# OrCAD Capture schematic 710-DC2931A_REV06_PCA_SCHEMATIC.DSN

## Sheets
1 PAGE2
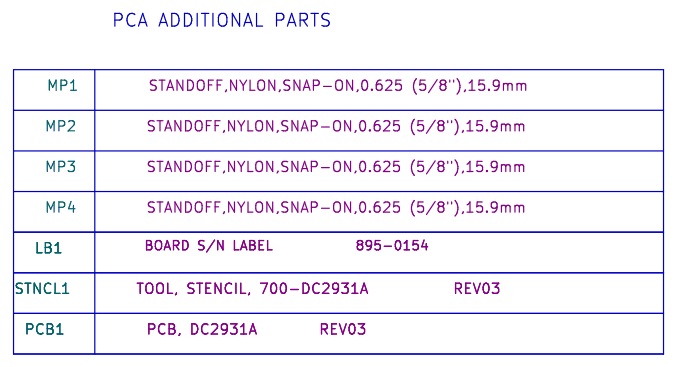
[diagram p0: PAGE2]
2 PAGE1: size Custom; note: HIGH EFFICIENCY BUCK-BOOST CONVERTER
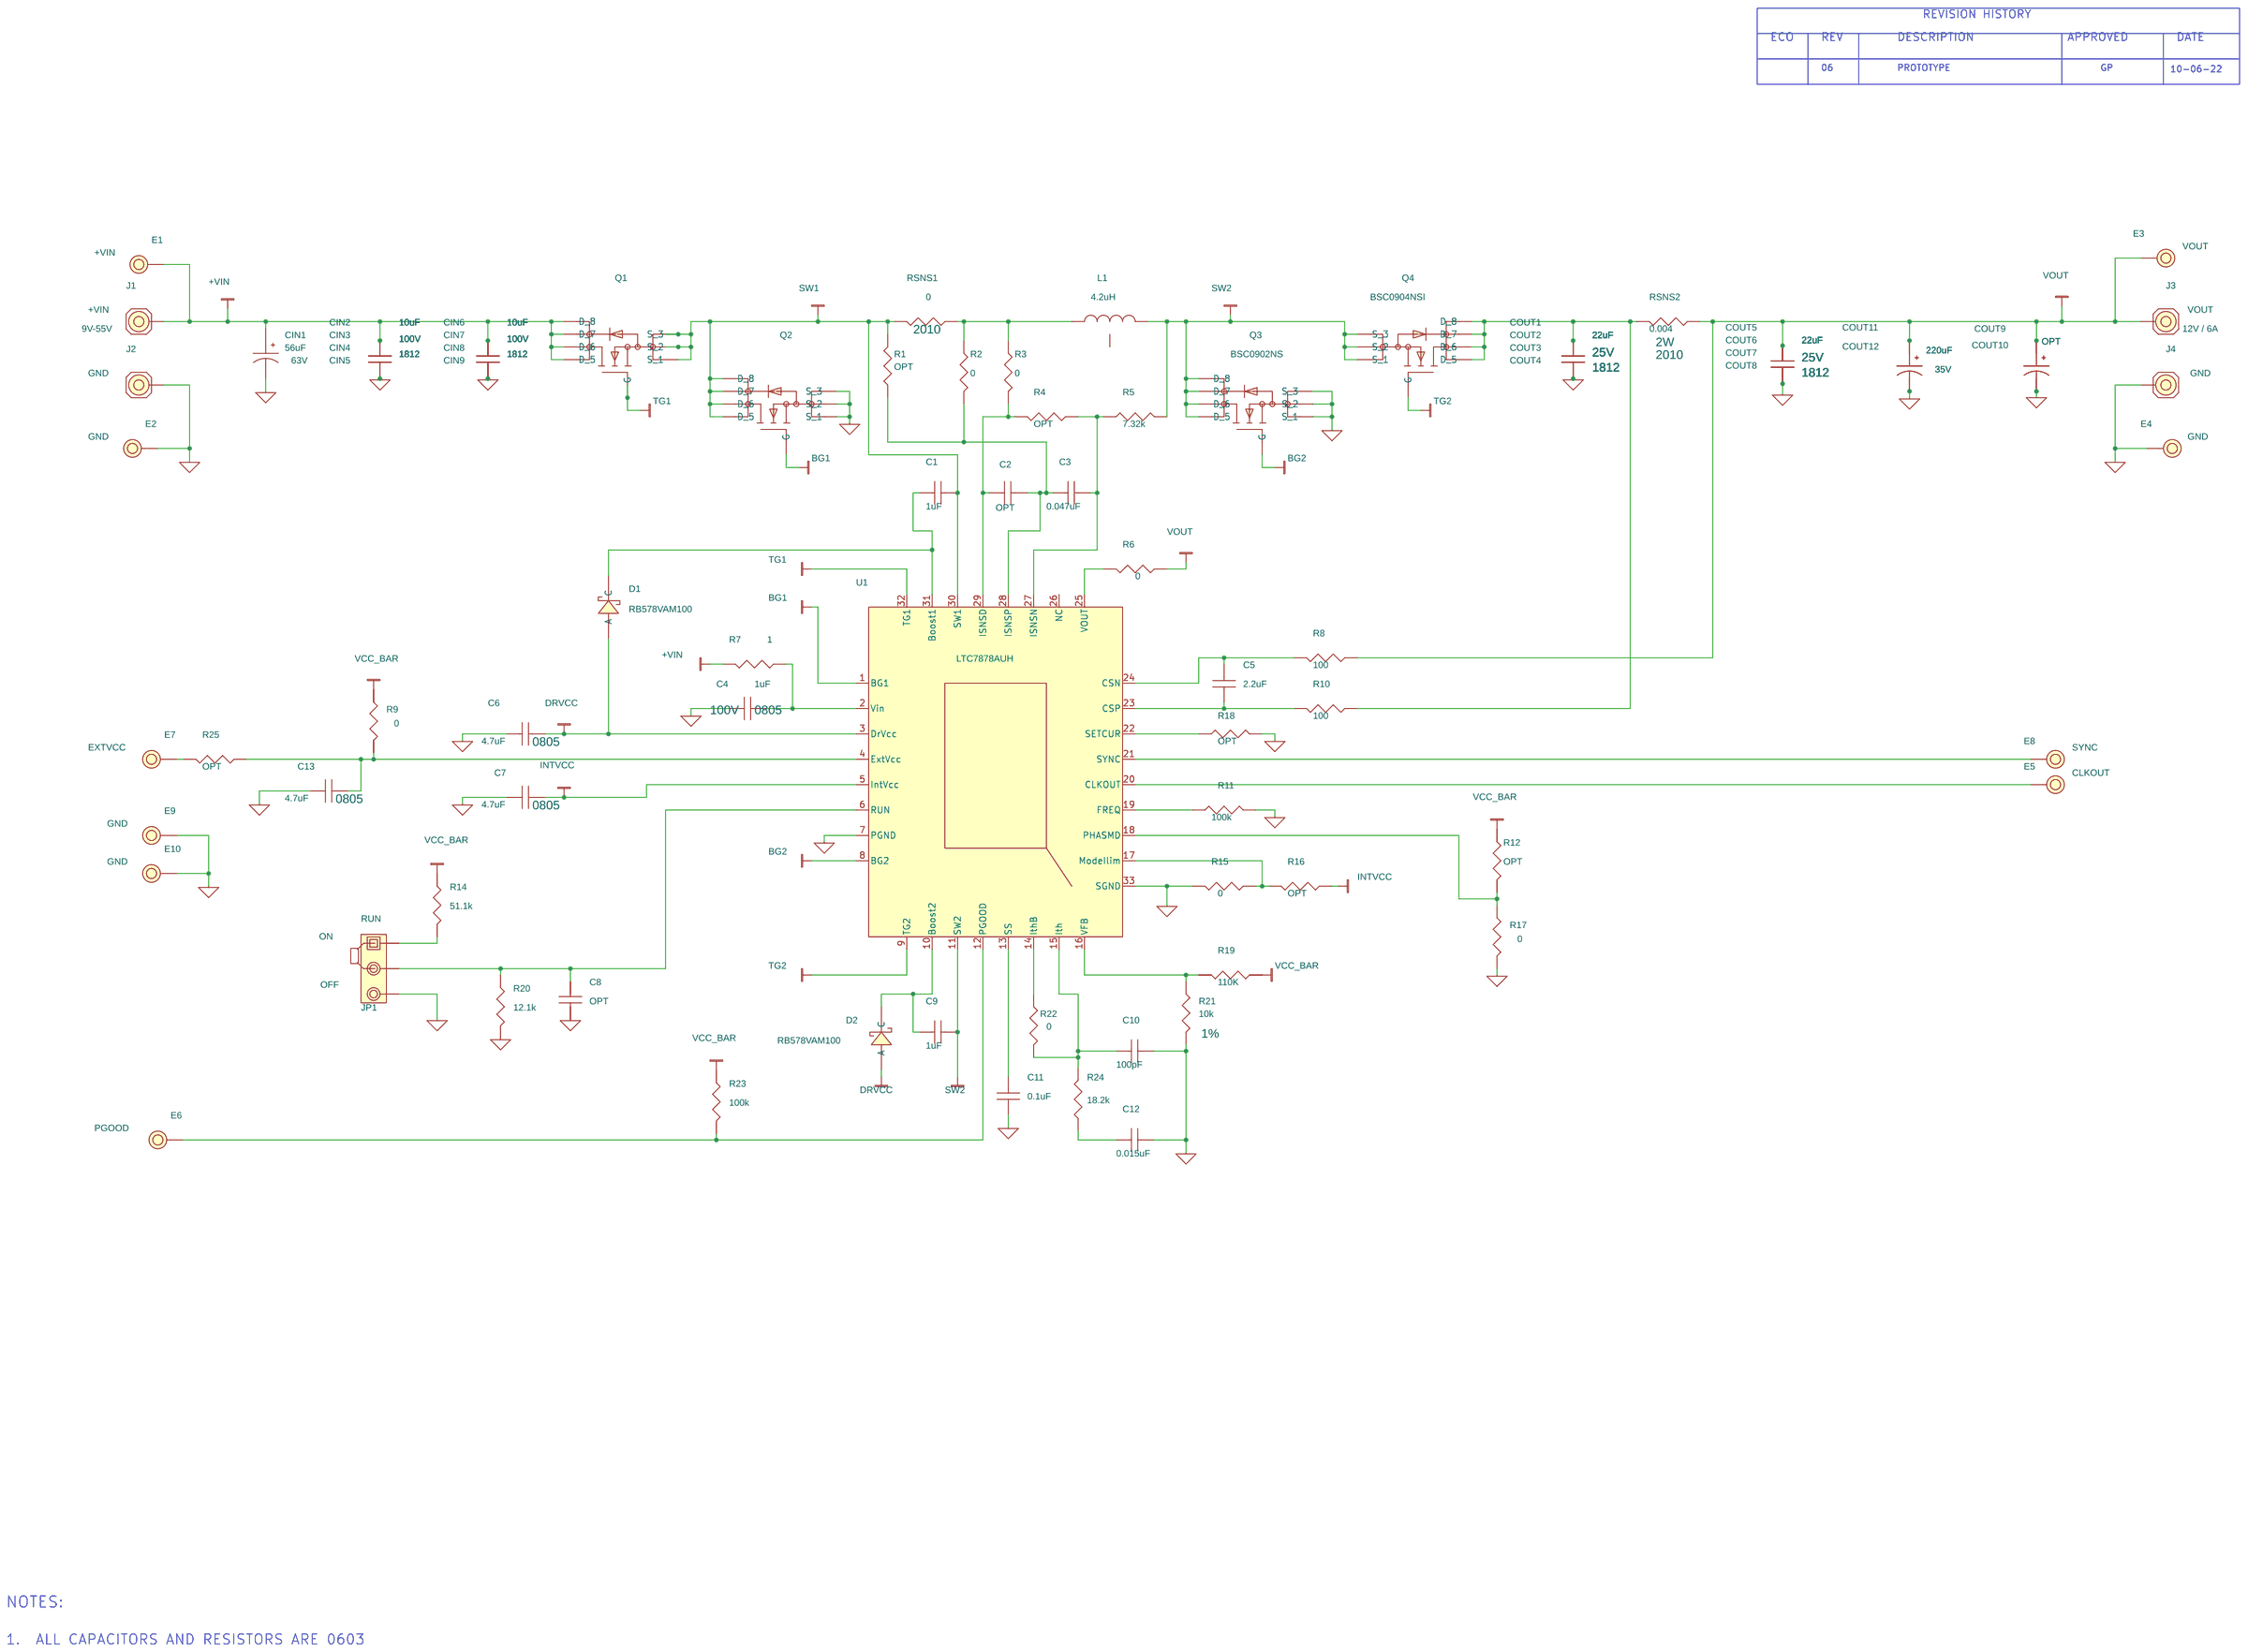
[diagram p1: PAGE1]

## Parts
sheet PAGE1
C1  1uF  [CC0603N]
C2  OPT  [CC0603N]
C3  0.047uF  [CC0603N]
C4  1uF  [CC0805N]
C5  2.2uF  [CC0603N]
C6  4.7uF  [CC0805N]
C7  4.7uF  [CC0805N]
C8  OPT  [CC0603N]
C9  1uF  [CC0603N]
C10  100pF  [CC0603N]
C11  0.1uF  [CC0603N]
C12  0.015uF  [CC0603N]
C13  4.7uF  [CC0805N]
CIN1  56uF  [PANASONIC_ZC_10X10.2]
CIN2  10uF  [CC1812N]
CIN3  10uF  [CC1812N]
CIN4  10uF  [CC1812N]
CIN5  10uF  [CC1812N]
CIN6  10uF  [CC1812N]
CIN7  10uF  [CC1812N]
CIN8  10uF  [CC1812N]
CIN9  10uF  [CC1812N]
COUT1  22uF  [CC1812N]
COUT2  22uF  [CC1812N]
COUT3  22uF  [CC1812N]
COUT4  22uF  [CC1812N]
COUT5  22uF  [CC1812N]
COUT6  22uF  [CC1812N]
COUT7  22uF  [CC1812N]
COUT8  22uF  [CC1812N]
COUT9  OPT  [USER_ASSIGNED]
COUT10  OPT  [USER_ASSIGNED]
COUT11  220uF  [SUNCON_HVH_10X12.5]
COUT12  220uF  [SUNCON_HVH_10X12.5]
D1  RB578VAM100  [ROHM-SOD-323HE]
D2  RB578VAM100  [ROHM-SOD-323HE]
E1  TEST POINT  [MILLMAX2501]
E2  TEST POINT  [MILLMAX2501]
E3  TEST POINT  [MILLMAX2501]
E4  TEST POINT  [MILLMAX2501]
E5  TEST POINT  [MILLMAX2501]
E6  TEST POINT  [MILLMAX2501]
E7  TEST POINT  [MILLMAX2501]
E8  TEST POINT  [MILLMAX2501]
E9  TEST POINT  [MILLMAX2501]
E10  TEST POINT  [MILLMAX2501]
J1  STUD,#10-32  [PENN-KFH-032]
J2  STUD,#10-32  [PENN-KFH-032]
J3  STUD,#10-32  [PENN-KFH-032]
J4  STUD,#10-32  [PENN-KFH-032]
JP1  HDR  [HD1X3-079]
L1  4.2uH  [WURTH-2013]
Q1  8P_N-CH_TYPE1A  [INFINEON-PG-TDSON-8]
Q2  8P_N-CH_TYPE1A  [INFINEON-PG-TDSON-8]
Q3  BSC0902NS  [INFINEON-PG-TDSON-8]
Q4  BSC0904NSI  [INFINEON-PG-TDSON-8]
R1  OPT  [CR0603N]
R2  0  [CR0603N]
R3  0  [CR0603N]
R4  OPT  [CR0603N]
R5  7.32k  [CR0603N]
R6  0  [CR0603N]
R7  1  [CR0603N]
R8  100  [CR0603N]
R9  0  [CR0603N]
R10  100  [CR0603N]
R11  100k  [CR0603N]
R12  OPT  [CR0603N]
R14  51.1k  [CR0603N]
R15  0  [CR0603N]
R16  OPT  [CR0603N]
R17  0  [CR0603N]
R18  OPT  [CR0603N]
R19  110K  [CR0603N]
R20  12.1k  [CR0603N]
R21  10k  [CR0603N]
R22  0  [CR0603N]
R23  100k  [CR0603N]
R24  18.2k  [CR0603N]
R25  OPT  [CR0603N]
RSNS1  0  [CR2010N]
RSNS2  0.004  [VISHAY-WSL2010_T58]
U1  LTC7878AUH  [LTC-UH-32-1693]
XJP1  SHUNT
sheet PAGE2
LB1  LABEL  [895-0154_REV01]
MP1  STANDOFF  [KEYSTONE_8829-8834]
MP2  STANDOFF  [KEYSTONE_8829-8834]
MP3  STANDOFF  [KEYSTONE_8829-8834]
MP4  STANDOFF  [KEYSTONE_8829-8834]
MP5  RING,LUG,#10,CRIMP
PCB1  PCB, DC2931A  [MECHANICAL_PART]
STNCL1  TOOL, STENCIL, 700-DC2931A

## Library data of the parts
C1 C9 = CAP: CAP.,1uF,X7R,16V,10%,0603; CLASS: DISCRETE; Dielectric Type: X7R; FPLIST: CC0603N,CC0603L,CC0603M; Inventory Qty: 29099; Manufacturer: KEMET; Manufacturer PN: C0603C105K4RAC7867; PART_NUMBER: 150-0179; Package Size: 0603; Rated Voltage: 16V; Tolerance: 10%
C2 C8 = CAP: CAP., OPTION, 0603; CLASS: DISCRETE; FPLIST: CC0603N,CC0603L,CC0603M; PART_NUMBER: 150-3038; Package Size: 0603; Package Type: SMD
C3 = CAP: CAP.,0.047uF,X7R,16V,10%,0603; CLASS: DISCRETE; Dielectric Type: X7R; FPLIST: CC0603N,CC0603L,CC0603M; Inventory Qty: 24676; Manufacturer: AVX; Manufacturer PN: 0603YC473KAT2A; PART_NUMBER: 150-3198; Package Size: 0603; Rated Voltage: 16V; Tolerance: 10%
C4 = CAP: CAP.,1uF,X7S,100V,20%,0805; CLASS: DISCRETE; Dielectric Type: X7S; FPLIST: CC0805N,CC0805L,CC0805M; Inventory Qty: 8512; Manufacturer: MURATA; Manufacturer PN: GRJ21BC72A105ME11L; PART_NUMBER: 150-2447; Package Size: 0805; Rated Voltage: 100V; Tolerance: 20%
C5 = CAP: CAP.,2.2uF,X5R,16V,10%,0603; CLASS: DISCRETE; Dielectric Type: X5R; FPLIST: CC0603N,CC0603L,CC0603M; Inventory Qty: 19450; Manufacturer: KEMET; Manufacturer PN: C0603C225K4PAC7867; PART_NUMBER: 150-0552; Package Size: 0603; Rated Voltage: 16V; Tolerance: 10%
C6 C7 C13 = CAP: CAP.,4.7uF,X5R,50V,10%,0805; CLASS: DISCRETE; Dielectric Type: X5R; FPLIST: CC0805N,CC0805L,CC0805M; Inventory Qty: 14038; Manufacturer: MURATA; Manufacturer PN: GRM21BR61H475KE51L; PART_NUMBER: 150-0172; Package Size: 0805; Rated Voltage: 50V; Tolerance: 10%
C10 = CAP: CAP.,100pF,X7R,25V,5%,0603; CLASS: DISCRETE; Dielectric Type: X7R; FPLIST: CC0603N,CC0603L,CC0603M; Inventory Qty: 38271; Manufacturer: AVX; Manufacturer PN: 06033C101JAT2A; PART_NUMBER: 150-0122; Package Size: 0603; Rated Voltage: 25V; Tolerance: 5%
C11 = CAP: CAP.,0.1uF,X7R,16V,10%,0603; CLASS: DISCRETE; Dielectric Type: X7R; FPLIST: CC0603N,CC0603L,CC0603M; Inventory Qty: 34669; Manufacturer: MURATA; Manufacturer PN: GRM188R71C104KA01D; PART_NUMBER: 150-0018; Package Size: 0603; Package Type: SMD; Rated Voltage: 16V; Tolerance: 10%
C12 = CAP: CAP.,0.015uF,X7R,25V,10%,0603; CLASS: DISCRETE; Dielectric Type: X7R; FPLIST: CC0603N,CC0603L,CC0603M; Inventory Qty: 32248; Manufacturer: AVX; Manufacturer PN: 06033C153KAT2A; PART_NUMBER: 150-3277; Package Size: 0603; Rated Voltage: 25V; Tolerance: 10%
CIN1 = CAP_P: CAP.,56uF,ALUM.ELECT.,63V,20%,10X10.2mm SMD, RADIAL,AEC-Q200; CLASS: DISCRETE; Dielectric Type: ALUM.ELECT.; Inventory Qty: 2000; Manufacturer: PANASONIC; Manufacturer PN: EEHZC1J560P; PART_NUMBER: 150-0727; Package Size: 10X10.2mm SMD, RADIAL; Rated Voltage: 63V; Tolerance: 20%
CIN2-CIN9 = CAP: CAP.,10uF,X7S,100V,20%,1812; CLASS: DISCRETE; Dielectric Type: X7S; FPLIST: CC1812N,CC1812L,CC1812M; Inventory Qty: 3000; Manufacturer: TDK; Manufacturer PN: CKG45NX7S2A106M500JH; PART_NUMBER: 150-0534; Package Size: 1812; Rated Voltage: 100V; Tolerance: 20%
COUT1-COUT8 = CAP: CAP.,22uF,X5R,25V,20%,1812; CLASS: DISCRETE; Dielectric Type: X5R; FPLIST: CC1812N,CC1812L,CC1812M; Inventory Qty: 4600; Manufacturer: TDK; Manufacturer PN: C4532X5R1E226M250KA; PART_NUMBER: 150-3272; Package Size: 1812; Rated Voltage: 25V; Tolerance: 20%
COUT9 COUT10 = CAP_P: CAP.,OPTION,ALUM. ELECT.,SMD; CLASS: DISCRETE; PART_NUMBER: 150-3568; Package Type: SMD
COUT11 COUT12 = CAP_P: CAP.,220uF,ALUM POLY HYB,35V,20%,10x12.5mm,SMD,RADIAL,HVH Series,AEC-Q200; CLASS: DISCRETE; Dielectric Type: ALUM POLY HYB; FPLIST: SUNCON_HVH_10X12.5,SUNCON_HVH_10X12-5; Inventory Qty: 5100; Manufacturer: SUN ELECTRONIC INDUSTRIES CORP; Manufacturer PN: 35HVH220M; PART_NUMBER: 150-0485; Package Size: 10x12.5mm,SMD,RADIAL; Rated Voltage: 35V; Tolerance: 20%
D1 D2 = DIODE_SCHOTTKY_A: DIODE,SCHOTTKY,100V,0.7A,SOD-323HE; CLASS: DISCRETE; Inventory Qty: 0; Manufacturer: ROHM; Manufacturer PN: RB578VAM100TR; PART_NUMBER: 210-0585; Package Size: 2-SMD, Flat Lead; Package Type: SOD-323HE; Rated Voltage or Zener Voltage: 100V
E1 = TESTPOINT_.219_MILL-MAX_2501: TEST POINT,TURRET,0.094" MTG. HOLE,PCB 0.062" THK; CLASS: IO; Inventory Qty: 823526; Manufacturer: MILL-MAX; Manufacturer PN: 2501-2-00-80-00-00-07-0; PART_FIELD_01: +VIN; PART_NUMBER: 260-0003
E2 E4 E9 E10 = TESTPOINT_.219_MILL-MAX_2501: TEST POINT,TURRET,0.094" MTG. HOLE,PCB 0.062" THK; CLASS: IO; Inventory Qty: 823526; Manufacturer: MILL-MAX; Manufacturer PN: 2501-2-00-80-00-00-07-0; PART_FIELD_01: GND; PART_NUMBER: 260-0003
E3 = TESTPOINT_.219_MILL-MAX_2501: TEST POINT,TURRET,0.094" MTG. HOLE,PCB 0.062" THK; CLASS: IO; Inventory Qty: 823526; Manufacturer: MILL-MAX; Manufacturer PN: 2501-2-00-80-00-00-07-0; PART_FIELD_01: VOUT; PART_NUMBER: 260-0003
E5 = TESTPOINT_.219_MILL-MAX_2501: TEST POINT,TURRET,0.094" MTG. HOLE,PCB 0.062" THK; CLASS: IO; Inventory Qty: 823526; Manufacturer: MILL-MAX; Manufacturer PN: 2501-2-00-80-00-00-07-0; PART_FIELD_01: CLKOUT; PART_NUMBER: 260-0003
E6 = TESTPOINT_.219_MILL-MAX_2501: TEST POINT,TURRET,0.094" MTG. HOLE,PCB 0.062" THK; CLASS: IO; Inventory Qty: 823526; Manufacturer: MILL-MAX; Manufacturer PN: 2501-2-00-80-00-00-07-0; PART_FIELD_01: PGOOD; PART_NUMBER: 260-0003
E7 = TESTPOINT_.219_MILL-MAX_2501: TEST POINT,TURRET,0.094" MTG. HOLE,PCB 0.062" THK; CLASS: IO; Inventory Qty: 823526; Manufacturer: MILL-MAX; Manufacturer PN: 2501-2-00-80-00-00-07-0; PART_FIELD_01: EXTVCC; PART_NUMBER: 260-0003
E8 = TESTPOINT_.219_MILL-MAX_2501: TEST POINT,TURRET,0.094" MTG. HOLE,PCB 0.062" THK; CLASS: IO; Inventory Qty: 823526; Manufacturer: MILL-MAX; Manufacturer PN: 2501-2-00-80-00-00-07-0; PART_FIELD_01: SYNC; PART_NUMBER: 260-0003
J1 = PEM-KFH: EVAL BOARD STUD HARDWARE SET, #10-32; 11th Part Field: +VIN; 9th Part Field: 9V-55V; CLASS: DISCRETE; Comments: CONSISTS OF QTY(1) STUD, 769-0012; QTY(1) RING LUG, 769-0013;QTY(2) HEX NUT,BRASS,761-0013; QTY(1) WASHER,#10 LOCK, 762-0021; Manufacturer: ANALOG DEVICES; Manufacturer PN: 769-0010; PART_NUMBER: 720-0010
J2 = PEM-KFH: EVAL BOARD STUD HARDWARE SET, #10-32; 11th Part Field: GND; 9th Part Field: 9V-55V; CLASS: DISCRETE; Comments: CONSISTS OF QTY(1) STUD, 769-0012; QTY(1) RING LUG, 769-0013;QTY(2) HEX NUT,BRASS,761-0013; QTY(1) WASHER,#10 LOCK, 762-0021; Manufacturer: ANALOG DEVICES; Manufacturer PN: 769-0010; PART_NUMBER: 720-0010
J3 = PEM-KFH: EVAL BOARD STUD HARDWARE SET, #10-32; 11th Part Field: VOUT; 9th Part Field: 12V / 6A; CLASS: DISCRETE; Comments: CONSISTS OF QTY(1) STUD, 769-0012; QTY(1) RING LUG, 769-0013;QTY(2) HEX NUT,BRASS,761-0013; QTY(1) WASHER,#10 LOCK, 762-0021; Manufacturer: ANALOG DEVICES; Manufacturer PN: 720-0010; PART_NUMBER: 720-0010
J4 = PEM-KFH: EVAL BOARD STUD HARDWARE SET, #10-32; 11th Part Field: GND; 9th Part Field: 9V-55V; CLASS: DISCRETE; Comments: CONSISTS OF QTY(1) STUD, 769-0012; QTY(1) RING LUG, 769-0013;QTY(2) HEX NUT,BRASS,761-0013; QTY(1) WASHER,#10 LOCK, 762-0021; Manufacturer: ANALOG DEVICES; Manufacturer PN: 720-0010; PART_NUMBER: 720-0010
JP1 = 1X3_A: CONN.,HDR,MALE,1x3,2mm,VERT,ST,THT,NO SUBS. ALLOWED; 11th Part Field: OFF; 12th Part Field: RUN; 9th Part Field: ON; CLASS: IO; Inventory Qty: 28997; Manufacturer: Wurth Elektronik; Manufacturer PN: 62000311121; PART_NUMBER: 250-0639
L1 = IND_3PIN_ALT: IND.,4.2uH,POWER CHOKE SHEILDED,15%,24A,3.04mOHMS,2013; CLASS: DISCRETE; Inventory Qty: 700; Manufacturer: WURTH ELEKTRONIK; Manufacturer PN: 7443630420; PART_NUMBER: 200-0603; Package Size: 2013; Tolerance: 15%
Q1 Q2 = 8P_N-CH_TYPE1A: XSTR.,MOSFET N-CHAN,60V,100A,8-pin TDSON; CLASS: DISCRETE; Inventory Qty: 380; Manufacturer: INFINEON; Manufacturer PN: BSC034N06NS; PART_NUMBER: 240-0241; Package Size: 8-PowerTDFN; Package Type: 8-pin TDSON; Polarity: N-Channel; Rated Voltage: 60V
Q3 = 8P_N-CH_TYPE1A: XSTR.,MOSFET,N-CH,30V,100A,PG-TDSON-8; CLASS: DISCRETE; Inventory Qty: 0; Manufacturer: INFINEON; PART_NUMBER: 240-0603; Package Size: 8-PowerTDFN; Package Type: PG-TDSON-8; Polarity: N-Channel; Rated Voltage: 30V
Q4 = 8P_N-CH_TYPE1A: XSTR.,MOSFET,N-CH,30V,78A,PG-TDSON-8; CLASS: DISCRETE; Inventory Qty: 0; Manufacturer: INFINEON; PART_NUMBER: 240-0604; Package Size: 8-PowerTDFN; Package Type: PG-TDSON-8; Polarity: N-Channel; Rated Voltage: 30V
R1 R4 R12 R16 R18 R25 = RES: RES., OPTION, 0603; CLASS: DISCRETE; FPLIST: CR0603N,CR0603L,CR0603M; PART_NUMBER: 100-2374; Package Size: 0603
R2 R3 R6 R9 R15 R17 R22 = RES: RES.,0 OHM,1/10W,0603,AEC-Q200; CLASS: DISCRETE; FPLIST: CR0603N,CR0603L,CR0603M; Inventory Qty: 676258; Manufacturer: VISHAY; Manufacturer PN: CRCW06030000Z0EA; PART_NUMBER: 100-0009; Package Size: 0603; Rated Power: 1/10W
R5 = RES: RES.,7.32k OHMS,1%,1/10W,0603; CLASS: DISCRETE; FPLIST: CR0603N,CR0603L,CR0603M; Inventory Qty: 5120; Manufacturer: PANASONIC; Manufacturer PN: ERJ3EKF7321V; PART_NUMBER: 100-2773; Package Size: 0603; Rated Power: 1/10W; Temperature Coefficient: 100ppm/C; Tolerance: 1%
R7 = RES: RES.,1 OHM,1%,1/10W,0603; CLASS: DISCRETE; FPLIST: CR0603N,CR0603L,CR0603M; Inventory Qty: 15524; Manufacturer: YAGEO; Manufacturer PN: RC0603FR-071RL; PART_NUMBER: 100-0163; Package Size: 0603; Rated Power: 1/10W; Temperature Coefficient: 200ppm/C; Tolerance: 1%
R8 R10 = RES: RES.,100 OHMS,1%,1/10W,0603; CLASS: DISCRETE; FPLIST: CR0603N,CR0603L,CR0603M; Inventory Qty: 70604; Manufacturer: YAGEO; Manufacturer PN: RC0603FR-07100RL; PART_NUMBER: 100-0150; Package Size: 0603; Rated Power: 1/10W; Temperature Coefficient: 100ppm/C; Tolerance: 1%
R11 R23 = RES: RES.,100k OHMS,5%,1/10W,0603,AEC-Q200; CLASS: DISCRETE; FPLIST: CR0603N,CR0603L,CR0603M; Inventory Qty: 48405; Manufacturer: NIC; Manufacturer PN: NRC06J104TRF; PART_NUMBER: 100-0312; Package Size: 0603; Rated Power: 1/10W; Temperature Coefficient: 200ppm/C; Tolerance: 5%
R14 = RES: RES.,51.1k OHMS,1%,1/10W,0603,AEC-Q200; CLASS: DISCRETE; FPLIST: CR0603N,CR0603L,CR0603M; Inventory Qty: 84370; Manufacturer: PANASONIC; Manufacturer PN: ERJ3EKF5112V; PART_NUMBER: 100-0508; Package Size: 0603; Rated Power: 1/10W; Temperature Coefficient: 100ppm; Tolerance: 1%
R19 = RES: RES.,110k OHMS,1%,1/10W,0603,AEC-Q200; CLASS: DISCRETE; FPLIST: CR0603N,CR0603L,CR0603M; Inventory Qty: 70777; Manufacturer: PANASONIC; Manufacturer PN: ERJ3EKF1103V; PART_NUMBER: 100-0789; Package Size: 0603; Rated Power: 1/10W; Temperature Coefficient: +/-100PPM; Tolerance: 1%
R20 = RES: RES.,12.1k OHMS,1%,1/10W,0603,AEC-Q200; CLASS: DISCRETE; FPLIST: CR0603N,CR0603L,CR0603M; Inventory Qty: 131843; Manufacturer: PANASONIC; Manufacturer PN: ERJ3EKF1212V; PART_NUMBER: 100-2655; Package Size: 0603; Rated Power: 1/10W; Temperature Coefficient: 100ppm/C; Tolerance: 1%
R21 = RES: RES.,10k OHMS,1%,1/10W,0603,AEC-Q200; CLASS: DISCRETE; FPLIST: CR0603N,CR0603L,CR0603M; Inventory Qty: 194448; Manufacturer: VISHAY; Manufacturer PN: CRCW060310K0FKEA; PART_NUMBER: 100-2012; Package Size: 0603; Rated Power: 1/10W; Temperature Coefficient: +/-100ppm/C; Tolerance: 1%
R24 = RES: RES.,18.2k OHMS,1%,1/10W,0603,AEC-Q200; CLASS: DISCRETE; Inventory Qty: 102564; Manufacturer: PANASONIC; Manufacturer PN: ERJ3EKF1822; PART_NUMBER: 100-2916; Package Size: 0603; Rated Power: 1/10W; Temperature Coefficient: +/-100ppm; Tolerance: 1%
RSNS1 = RES: RES.,0 OHM,JUMPER,75A,2010,COPPER,SENSE; CLASS: DISCRETE; FPLIST: CR2010N,CR2010L,CR2010M; Inventory Qty: 14336; Manufacturer: VISHAY; Manufacturer PN: WSL201000000ZEA9; PART_NUMBER: 100-2028; Package Size: 2010; Rated Power: 75A; Temperature Coefficient: +/-3900ppm; Tolerance: JUMPER
RSNS2 = RES: RES.,0.004 OHMS,1%,2W,2010; CLASS: DISCRETE; FPLIST: CR2010N,CR2010L,CR2010M; Inventory Qty: 4000; Manufacturer: VISHAY; Manufacturer PN: WSL20104L000FEA; PART_NUMBER: 100-2745; Package Size: 2010; Rated Power: 2W; Temperature Coefficient: 150ppm/C; Tolerance: 1%
U1 = LTC7878EUH: IC, 70V PARALLELABLE 4 SWITCH BUCK-BOOST CONTROLLER; CLASS: IC; Inventory Qty: 0; Manufacturer: ANALOG DEVICES; Manufacturer PN: LTC7878AUH#PBF; PART_NUMBER: LTC7878AUH#PBF
XJP1 = SHUNT_2MM: CONN.,SHUNT,FEMALE,2-POS,2mm; CLASS: IO; Inventory Qty: 64675; Manufacturer: Wurth Elektronik; Manufacturer PN: 60800213421; PART_NUMBER: 250-0485
LB1 = BLANK_LABEL: LABEL SPEC, DEMO BOARD SERIAL NUMBER; Inventory Qty: 0; Manufacturer: BRADY; Manufacturer PN: THT-96-717-10; PART_FIELD_01: BOARD S/N LABEL; PART_NUMBER: 895-0154
MP1-MP4 = BLANK_PINLESS_MECHANICAL_PART: STANDOFF,NYLON,SNAP-ON,0.625 (5/8"),15.9mm; CLASS: DISCRETE; Inventory Qty: 185253; Manufacturer: KEYSTONE; Manufacturer PN: 8834; PART_NUMBER: 763-0013
MP5 = BLANK_PINLESS_MECHANICAL_PART: RING,LUG,#10,CRIMP,16/14 AWG,NON-INSULATED,SOLDERLESS TERMINALS; CLASS: DISCRETE; Inventory Qty: 71974; Manufacturer: KEYSTONE; Manufacturer PN: 8205; PART_NUMBER: 769-0010
PCB1 = BLANK_PCB_PART: BOM Notes: REV03; CLASS: DISCRETE; Inventory Qty: 0; Manufacturer: ADI APPROVED SUPPLIER; Manufacturer PN: 600-DC2931A; PART_NUMBER: 600-DC2931A
STNCL1 = BLANK_STENCIL_PART: BOM Notes: REV03; CLASS: DISCRETE; Inventory Qty: 0; Manufacturer: ANALOG DEVICES; Manufacturer PN: 830-DC2931A; PART_NUMBER: 830-DC2931A

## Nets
+VIN: CIN1.1 CIN2.1 CIN3.1 CIN4.1 CIN5.1 CIN6.1 CIN7.1 CIN8.1 CIN9.1 E1.1 J1.1 Q1.5(D) Q1.6(D) Q1.7(D) Q1.8(D) R7.1 R14.1
GND: C4.1 C6.1 C7.1 C8.2 C10.2 C11.1 C12.2 C13.1 CIN1.2 CIN2.2 CIN3.2 CIN4.2 CIN5.2 CIN6.2 CIN7.2 CIN8.2 CIN9.2 COUT1.2 COUT2.2 COUT3.2 COUT4.2 COUT5.2 COUT6.2 COUT7.2 COUT8.2 COUT9.2 COUT10.2 COUT11.2 COUT12.2 E2.1 E4.1 E9.1 E10.1 J2.1 J4.1 JP1.3 Q2.1(S) Q2.2(S) Q2.3(S) Q3.1(S) Q3.2(S) Q3.3(S) R11.2 R15.1 R17.1 R18.1 R20.2 R21.1 U1.7(PGND) U1.33(SGND)
BG1: Q2.4(G) U1.1(BG1)
BG2: Q3.4(G) U1.8(BG2)
DRVCC: C6.2 D1.2(A) D2.2(A) U1.3(DrVcc)
INTVCC: C7.2 R12.2 R16.2 R23.2 U1.5(IntVcc)
SW1: C1.2 Q1.1(S) Q1.2(S) Q1.3(S) Q2.5(D) Q2.6(D) Q2.7(D) Q2.8(D) R1.2 RSNS1.2 U1.30(SW1)
SW2: C9.2 L1.2 Q3.5(D) Q3.6(D) Q3.7(D) Q3.8(D) Q4.1(S) Q4.2(S) Q4.3(S) R5.2 U1.11(SW2)
TG1: Q1.4(G) U1.32(TG1)
TG2: Q4.4(G) U1.9(TG2)
VOUT: COUT5.1 COUT6.1 COUT7.1 COUT8.1 COUT9.1 COUT10.1 COUT11.1 COUT12.1 E3.1 J3.1 R6.2 R8.2 R9.1 R19.2 RSNS2.1
N17014400: C8.1 JP1.2 R20.1 U1.6(RUN)
N17559530: JP1.1 R14.2
N17560975: C13.2 R9.2 R25.1 U1.4(ExtVcc)
N17561731: C1.1 D1.1(C) U1.31(Boost1)
N17565162: L1.1 R2.1 R3.1 RSNS1.1
N17565268: C2.1 R3.2 R4.1 U1.29(ISNSD)
N17565335: C2.2 C3.1 R1.1 R2.2 U1.28(ISNSP)
N17565600: C3.2 R4.2 R5.1 U1.27(ISNSN)
N17567591: COUT1.1 COUT2.1 COUT3.1 COUT4.1 Q4.5(D) Q4.6(D) Q4.7(D) Q4.8(D) R10.2 RSNS2.2
N17570016: C5.1 R10.1 U1.23(CSP)
N17570021: C5.2 R8.1 U1.24(CSN)
N17570264: E8.1 U1.21(SYNC)
N17570273: E5.1 U1.20(CLKOUT)
N17570282: R18.2 U1.22(SETCUR)
N17570304: R11.1 U1.19(FREQ)
N17570418: R12.1 R17.2 U1.18(PHASMD)
N17570751: R15.2 R16.1 U1.17(ModeIlim)
N17571953: C9.1 D2.1(C) U1.10(Boost2)
N17572161: E6.1 R23.1 U1.12(PGOOD)
N17572245: C11.2 U1.13(SS)
N17572431: R22.2 U1.14(IthB)
N17572499: C10.1 R22.1 R24.2 U1.15(Ith)
N17572504: R19.1 R21.2 U1.16(VFB)
N17572848: C12.1 R24.1
N17613982: R6.1 U1.25(VOUT)
N17614759: C4.2 R7.2 U1.2(Vin)
N17644524: E7.1 R25.2

Not connected (* = marked no-connect by the designer): L1 3; U1 26(NC)

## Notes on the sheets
sheet 1
- PCA ADDITIONAL PARTS
sheet 2
- REVISION HISTORY
- ECO
- REV
- DESCRIPTION
- APPROVED
- DATE
- 06
- PROTOTYPE
- GP
- 10-06-22
- NOTES:
- 1.  ALL CAPACITORS AND RESISTORS ARE 0603
